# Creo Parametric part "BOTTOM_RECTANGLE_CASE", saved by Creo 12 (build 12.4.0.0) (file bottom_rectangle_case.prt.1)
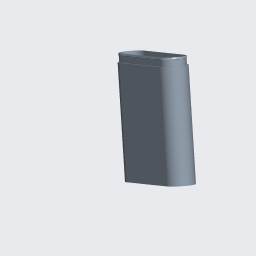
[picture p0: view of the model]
Units: Inch lbm Second (Pro/E Default); INCH, POUND, SECS

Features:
  1. datum plane "RIGHT"
  2. datum plane "TOP"
  3. datum plane "FRONT"
  4. coordinate system
  5. protrusion
  6. protrusion
  7. cut
  8. chamfer
  9. cut
  10. round
  11. round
